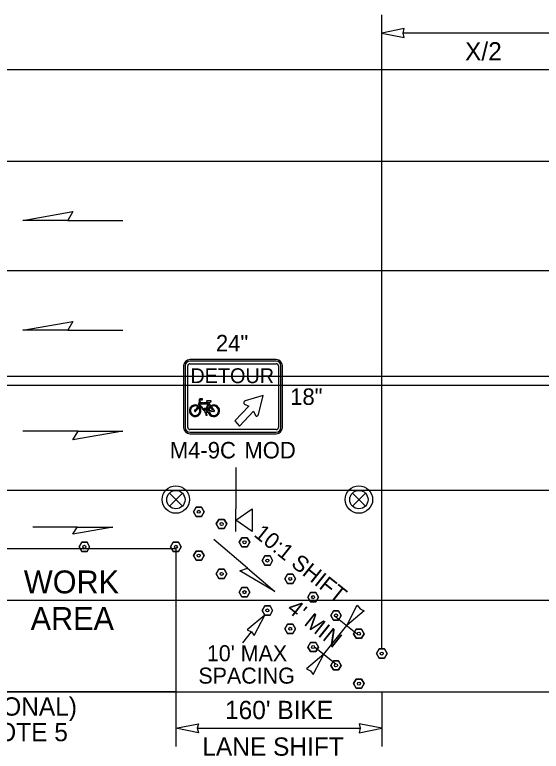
# Model space of a CAD drawing. Extents: x 99958 to 100176, y 99935 to 100011.
# Drawn here: x 100031.459 to 100033.761, y 99944.475 to 99947.696 of the extents above; entities that cross this region are included whole.
import ezdxf

# ---------------------------------------------------------------- set-up
doc = ezdxf.new("R2010")
doc.units = 0
for name, color, linetype in [('RD_ED_ShoulderPavedEdge', 7, 'Continuous'), ('RD_MK_LineDblYellowCenter', 7, 'Continuous'), ('RD_MK_LineEdgeWhite', 7, 'Continuous'), ('RD_MK_LineLane', 7, 'Continuous'), ('TR_SN_ConstructionSigns', 7, 'Continuous'), ('TR_WZ_PortableSignMountBlk-Org', 7, 'Continuous'), ('TR_WZ_TrafficSafetyDrum', 7, 'Continuous'), ('TR_WZ_TubularMarker', 7, 'Continuous'), ('TR_WZ_WorkAreaLabel', 7, 'Continuous'), ('TR_WZ_WorkZoneDetails', 7, 'Continuous'), ('TR_WZ_WorkZoneTextCurrent', 7, 'Continuous')]:
    doc.layers.add(name, color=color, linetype=linetype)

msp = doc.modelspace()

# ---------------------------------------------------------------- linework, layer by layer
at = {"layer": 'RD_ED_ShoulderPavedEdge'}
for p, q in [((100021.7266, 99947.4557), (100034.8933, 99947.4557)), ((100021.7266, 99944.7357), (100034.8933, 99944.7357))]:
    msp.add_line(p, q, dxfattribs=at)
at = {"layer": 'RD_MK_LineDblYellowCenter'}
for p, q in [((100021.7473, 99946.1157), (100034.914, 99946.1157)), ((100021.706, 99946.0757), (100034.8726, 99946.0757))]:
    msp.add_line(p, q, dxfattribs=at)
at = {"layer": 'RD_MK_LineEdgeWhite'}
for p, q in [((100021.7266, 99947.0557), (100034.8933, 99947.0557)), ((100021.7266, 99945.1357), (100034.8933, 99945.1357))]:
    msp.add_line(p, q, dxfattribs=at)
at = {"layer": 'RD_MK_LineLane'}
for points in [[(100034.8933, 99946.5757), (100021.7266, 99946.5757)], [(100034.8933, 99945.6157), (100021.7266, 99945.6157)]]:
    msp.add_lwpolyline(points, dxfattribs=at)
at = {"layer": 'TR_SN_ConstructionSigns'}
for p, q in [((100032.6025, 99946.1877), (100032.2245, 99946.1877)), ((100032.1975, 99946.1607), (100032.1975, 99945.8907)), ((100032.2042, 99946.1607), (100032.2042, 99945.8907)), ((100032.2155, 99945.8907), (100032.2155, 99946.1607)), ((100032.6025, 99946.181), (100032.2245, 99946.181)), ((100032.2245, 99946.1697), (100032.6025, 99946.1697)), ((100032.6115, 99946.1607), (100032.6115, 99945.8907)), ((100032.6227, 99945.8907), (100032.6227, 99946.1607)), ((100032.6295, 99945.8907), (100032.6295, 99946.1607)), ((100032.2675, 99946.0076), (100032.2604, 99945.9864)), ((100032.269, 99946.0156), (100032.2643, 99946.0108)), ((100032.2643, 99946.0108), (100032.2675, 99946.0076)), ((100032.2666, 99945.992), (100032.2675, 99945.9946)), ((100032.2675, 99945.9946), (100032.3033, 99945.9946)), ((100032.2802, 99946.0156), (100032.269, 99946.0156)), ((100032.269, 99945.9991), (100032.2718, 99946.0076)), ((100032.3048, 99945.9991), (100032.269, 99945.9991)), ((100032.2691, 99946.0103), (100032.2706, 99946.0118)), ((100032.2718, 99946.0076), (100032.2691, 99946.0103)), ((100032.2706, 99946.0118), (100032.2802, 99946.0118)), ((100032.2802, 99946.0118), (100032.2802, 99946.0156)), ((100032.3033, 99945.9946), (100032.2935, 99945.9651)), ((100032.2978, 99946.0041), (100032.298, 99946.0039)), ((100032.3156, 99946.0079), (100032.2987, 99946.0068)), ((100032.3056, 99946.0014), (100032.3048, 99945.9991)), ((100032.309, 99945.9975), (100032.3072, 99945.9922)), ((100032.3166, 99945.9863), (100032.309, 99945.9975)), ((100032.3168, 99946.0036), (100032.317, 99946.0038)), ((100032.247, 99945.9675), (100032.247, 99945.9676)), ((100032.2512, 99945.9651), (100032.2511, 99945.9651)), ((100032.2589, 99945.9821), (100032.2589, 99945.9821)), ((100032.2639, 99945.984), (100032.2624, 99945.9794)), ((100032.265, 99945.9872), (100032.2666, 99945.992)), ((100032.2902, 99945.9664), (100032.2666, 99945.992)), ((100032.2938, 99945.9737), (100032.2879, 99945.9737)), ((100032.2893, 99945.9715), (100032.2902, 99945.9664)), ((100032.2935, 99945.9651), (100032.2923, 99945.9715)), ((100032.2923, 99945.9715), (100032.2938, 99945.9715)), ((100032.2938, 99945.9715), (100032.2938, 99945.9737)), ((100032.2972, 99945.962), (100032.3072, 99945.9922)), ((100032.304, 99945.963), (100032.2972, 99945.962)), ((100032.3072, 99945.9922), (100032.313, 99945.9837)), ((100032.3249, 99945.9662), (100032.3084, 99945.9637)), ((100032.309, 99945.9593), (100032.327, 99945.9619)), ((100032.313, 99945.9837), (100032.3155, 99945.98)), ((100032.3155, 99945.98), (100032.313, 99945.9837)), ((100032.3155, 99945.98), (100032.3249, 99945.9662)), ((100032.3293, 99945.9677), (100032.3192, 99945.9826)), ((100032.2929, 99945.9546), (100032.2953, 99945.9472)), ((100032.2953, 99945.9472), (100032.2941, 99945.9472)), ((100032.2941, 99945.9472), (100032.2941, 99945.945)), ((100032.2941, 99945.945), (100032.3001, 99945.945)), ((100032.2985, 99945.9472), (100032.2957, 99945.9555)), ((100032.2969, 99945.9575), (100032.3046, 99945.9586)), ((100032.3001, 99945.9472), (100032.2985, 99945.9472)), ((100032.3001, 99945.945), (100032.3001, 99945.9472)), ((100032.3046, 99945.9586), (100032.309, 99945.9593)), ((100032.309, 99945.9593), (100032.3046, 99945.9586)), ((100032.6025, 99945.8817), (100032.2245, 99945.8817)), ((100032.2245, 99945.8705), (100032.6025, 99945.8705)), ((100032.2245, 99945.8637), (100032.6025, 99945.8637))]:
    msp.add_line(p, q, dxfattribs=at)
for points in [[(100032.5454, 99946.0301), (100032.4664, 99946.0069), (100032.4653, 99946.0065), (100032.4635, 99946.0053), (100032.4623, 99946.0039), (100032.4613, 99946.0021), (100032.4606, 99945.9997), (100032.4608, 99945.9973), (100032.4613, 99945.9958), (100032.4625, 99945.9942), (100032.4641, 99945.9932), (100032.4819, 99945.9848), (100032.4209, 99945.9198), (100032.442, 99945.8973), (100032.5027, 99945.962), (100032.5115, 99945.9436), (100032.512, 99945.9429), (100032.5127, 99945.942), (100032.5134, 99945.9415), (100032.5142, 99945.941), (100032.5153, 99945.9407), (100032.5163, 99945.9406), (100032.5175, 99945.9407), (100032.5194, 99945.9413), (100032.5204, 99945.9418), (100032.5212, 99945.9424), (100032.5221, 99945.9433), (100032.5231, 99945.9446), (100032.5237, 99945.9458), (100032.5242, 99945.9473), (100032.5454, 99946.0301)], [(100032.2978, 99946.0041), (100032.2978, 99946.0041)], [(100032.298, 99946.0039), (100032.298, 99946.0039)], [(100032.3072, 99945.9922), (100032.309, 99945.9975), (100032.3104, 99946.0015)], [(100032.3168, 99946.0036), (100032.3168, 99946.0036)], [(100032.317, 99946.0038), (100032.317, 99946.0038)], [(100032.2624, 99945.9794), (100032.2639, 99945.984), (100032.265, 99945.9872)], [(100032.2666, 99945.992), (100032.265, 99945.9872), (100032.29, 99945.9601)], [(100032.2879, 99945.9737), (100032.2879, 99945.9715), (100032.2893, 99945.9715)]]:
    msp.add_lwpolyline(points, dxfattribs=at)
for centre, radius, start, end in [((100032.2245, 99946.1607), 0.027, 90, 180), ((100032.6025, 99946.1607), 0.027, 360, 90), ((100032.2245, 99946.1607), 0.0203, 90, 180), ((100032.2245, 99946.1607), 0.009, 90, 180), ((100032.6025, 99946.1607), 0.0203, 0, 90), ((100032.6025, 99946.1607), 0.009, 360, 90), ((100032.2987, 99946.0053), 0.00149, 89.3854, 233.368), ((100032.3159, 99946.0057), 0.00224, 301.1219, 96.4128), ((100032.2479, 99945.9643), 0.0254, 60.5529, 50.868), ((100032.2479, 99945.9643), 0.0209, 58.1532, 46.1649), ((100032.2479, 99945.9643), 0.00336, 105.257, 14.3233), ((100032.3293, 99945.9643), 0.0254, 130.0889, 182.8379), ((100032.3293, 99945.9643), 0.0254, 192.9622, 119.9648), ((100032.3293, 99945.9643), 0.0209, 131.3616, 181.6359), ((100032.3293, 99945.9643), 0.0209, 193.937, 119.0598), ((100032.3293, 99945.9643), 0.00336, 225.1095, 90.4672), ((100032.2932, 99945.9583), 0.00374, 151.1744, 264.8566), ((100032.2932, 99945.9583), 0.00374, 312.0053, 347.2932), ((100032.2245, 99945.8907), 0.027, 180, 270), ((100032.2245, 99945.8907), 0.0202, 180, 270), ((100032.2245, 99945.8907), 0.009, 180, 270), ((100032.6025, 99945.8907), 0.027, 270, 0), ((100032.6025, 99945.8907), 0.0203, 270, 0), ((100032.6025, 99945.8907), 0.009, 270, 0)]:
    msp.add_arc(centre, radius, start, end, dxfattribs=at)
for centre, major_axis, ratio, start_param, end_param in [((100032.3076, 99946.0088), (-0.0127, 0), 0.588235, 0.712928, 1.410588), ((100032.3076, 99946.0088), (-0.0127, 0), 0.588235, 1.786993, 2.376237), ((100032.2512, 99945.9784), (-0.0072, -0.0108), 0.413554, 0.494612, 2.170849), ((100032.2512, 99945.9784), (-0.0095, -0.0143), 0.55814, 0.868091, 1.989998)]:
    msp.add_ellipse(centre, major_axis=major_axis, ratio=ratio, start_param=start_param, end_param=end_param, dxfattribs=at)
at = {"layer": 'TR_WZ_PortableSignMountBlk-Org'}
msp.add_line((100032.4251, 99945.4357), (100032.4251, 99945.5357), dxfattribs=at)
msp.add_lwpolyline([(100032.4251, 99945.4856), (100032.4969, 99945.5357), (100032.4969, 99945.4357)], close=True, dxfattribs=at)
at = {"layer": 'TR_WZ_TrafficSafetyDrum'}
for p, q in [((100032.1353, 99945.604), (100032.1919, 99945.5474)), ((100032.1919, 99945.604), (100032.1353, 99945.5474)), ((100032.1353, 99945.604), (100032.1919, 99945.5474)), ((100032.1919, 99945.604), (100032.1353, 99945.5474)), ((100032.9353, 99945.604), (100032.9919, 99945.5474)), ((100032.9919, 99945.604), (100032.9353, 99945.5474)), ((100032.9353, 99945.604), (100032.9919, 99945.5474)), ((100032.9919, 99945.604), (100032.9353, 99945.5474))]:
    msp.add_line(p, q, dxfattribs=at)
for centre, radius in [((100032.1636, 99945.5757), 0.06), ((100032.1636, 99945.5757), 0.06), ((100032.1636, 99945.5757), 0.06), ((100032.1636, 99945.5757), 0.06), ((100032.1636, 99945.5757), 0.04), ((100032.1636, 99945.5757), 0.04), ((100032.9636, 99945.5757), 0.06), ((100032.9636, 99945.5757), 0.06), ((100032.9636, 99945.5757), 0.06), ((100032.9636, 99945.5757), 0.06), ((100032.9636, 99945.5757), 0.04), ((100032.9636, 99945.5757), 0.04)]:
    msp.add_circle(centre, radius, dxfattribs=at)
at = {"layer": 'TR_WZ_TubularMarker'}
for points in [[(100032.2867, 99945.5224), (100032.2751, 99945.5424), (100032.252, 99945.5424), (100032.2405, 99945.5224), (100032.252, 99945.5024), (100032.2751, 99945.5024)], [(100032.3866, 99945.469), (100032.3751, 99945.489), (100032.352, 99945.489), (100032.3404, 99945.469), (100032.352, 99945.449), (100032.3751, 99945.449)], [(100031.7405, 99945.3691), (100031.7521, 99945.3891), (100031.7752, 99945.3891), (100031.7867, 99945.3691), (100031.7752, 99945.3491), (100031.7521, 99945.3491)], [(100032.1405, 99945.3691), (100032.1521, 99945.3891), (100032.1752, 99945.3891), (100032.1867, 99945.3691), (100032.1752, 99945.3491), (100032.1521, 99945.3491)], [(100032.4866, 99945.389), (100032.4751, 99945.409), (100032.452, 99945.409), (100032.4404, 99945.389), (100032.452, 99945.369), (100032.4751, 99945.369)], [(100032.2866, 99945.3308), (100032.2751, 99945.3508), (100032.252, 99945.3508), (100032.2404, 99945.3308), (100032.252, 99945.3108), (100032.2751, 99945.3108)], [(100032.5866, 99945.309), (100032.5751, 99945.329), (100032.552, 99945.329), (100032.5404, 99945.309), (100032.552, 99945.289), (100032.5751, 99945.289)], [(100032.3866, 99945.2508), (100032.3751, 99945.2708), (100032.352, 99945.2708), (100032.3404, 99945.2508), (100032.352, 99945.2308), (100032.3751, 99945.2308)], [(100032.6866, 99945.229), (100032.6751, 99945.249), (100032.652, 99945.249), (100032.6404, 99945.229), (100032.652, 99945.209), (100032.6751, 99945.209)], [(100032.4866, 99945.1708), (100032.4751, 99945.1908), (100032.452, 99945.1908), (100032.4404, 99945.1708), (100032.452, 99945.1508), (100032.4751, 99945.1508)], [(100032.7866, 99945.149), (100032.7751, 99945.169), (100032.752, 99945.169), (100032.7404, 99945.149), (100032.752, 99945.129), (100032.7751, 99945.129)], [(100032.5866, 99945.0908), (100032.5751, 99945.1108), (100032.552, 99945.1108), (100032.5404, 99945.0908), (100032.552, 99945.0708), (100032.5751, 99945.0708)], [(100032.8866, 99945.0691), (100032.8751, 99945.0891), (100032.852, 99945.0891), (100032.8404, 99945.0691), (100032.852, 99945.0491), (100032.8751, 99945.0491)], [(100032.6866, 99945.0108), (100032.6751, 99945.0308), (100032.652, 99945.0308), (100032.6404, 99945.0108), (100032.652, 99944.9908), (100032.6751, 99944.9908)], [(100032.9866, 99944.9891), (100032.9751, 99945.0091), (100032.952, 99945.0091), (100032.9404, 99944.9891), (100032.952, 99944.9691), (100032.9751, 99944.9691)], [(100032.7866, 99944.9308), (100032.7751, 99944.9508), (100032.752, 99944.9508), (100032.7404, 99944.9308), (100032.752, 99944.9108), (100032.7751, 99944.9108)], [(100033.0866, 99944.9024), (100033.0751, 99944.9224), (100033.052, 99944.9224), (100033.0404, 99944.9024), (100033.052, 99944.8824), (100033.0751, 99944.8824)], [(100032.8866, 99944.8508), (100032.8751, 99944.8708), (100032.852, 99944.8708), (100032.8404, 99944.8508), (100032.852, 99944.8308), (100032.8751, 99944.8308)], [(100032.9866, 99944.7708), (100032.9751, 99944.7908), (100032.952, 99944.7908), (100032.9404, 99944.7708), (100032.952, 99944.7508), (100032.9751, 99944.7508)]]:
    msp.add_lwpolyline(points, close=True, dxfattribs=at)
for points in [[(100032.2751, 99945.5024), (100032.252, 99945.5024), (100032.2405, 99945.5224), (100032.252, 99945.5424), (100032.2751, 99945.5424), (100032.2867, 99945.5224), (100032.2751, 99945.5024)], [(100032.3751, 99945.449), (100032.352, 99945.449), (100032.3404, 99945.469), (100032.352, 99945.489), (100032.3751, 99945.489), (100032.3866, 99945.469), (100032.3751, 99945.449)], [(100031.7521, 99945.3491), (100031.7752, 99945.3491), (100031.7867, 99945.3691), (100031.7752, 99945.3891), (100031.7521, 99945.3891), (100031.7405, 99945.3691), (100031.7521, 99945.3491)], [(100032.1521, 99945.3491), (100032.1752, 99945.3491), (100032.1867, 99945.3691), (100032.1752, 99945.3891), (100032.1521, 99945.3891), (100032.1405, 99945.3691), (100032.1521, 99945.3491)], [(100032.4751, 99945.369), (100032.452, 99945.369), (100032.4404, 99945.389), (100032.452, 99945.409), (100032.4751, 99945.409), (100032.4866, 99945.389), (100032.4751, 99945.369)], [(100032.2751, 99945.3108), (100032.252, 99945.3108), (100032.2404, 99945.3308), (100032.252, 99945.3508), (100032.2751, 99945.3508), (100032.2866, 99945.3308), (100032.2751, 99945.3108)], [(100032.5751, 99945.289), (100032.552, 99945.289), (100032.5404, 99945.309), (100032.552, 99945.329), (100032.5751, 99945.329), (100032.5866, 99945.309), (100032.5751, 99945.289)], [(100032.3751, 99945.2308), (100032.352, 99945.2308), (100032.3404, 99945.2508), (100032.352, 99945.2708), (100032.3751, 99945.2708), (100032.3866, 99945.2508), (100032.3751, 99945.2308)], [(100032.6751, 99945.209), (100032.652, 99945.209), (100032.6404, 99945.229), (100032.652, 99945.249), (100032.6751, 99945.249), (100032.6866, 99945.229), (100032.6751, 99945.209)], [(100032.4751, 99945.1508), (100032.452, 99945.1508), (100032.4404, 99945.1708), (100032.452, 99945.1908), (100032.4751, 99945.1908), (100032.4866, 99945.1708), (100032.4751, 99945.1508)], [(100032.7751, 99945.129), (100032.752, 99945.129), (100032.7404, 99945.149), (100032.752, 99945.169), (100032.7751, 99945.169), (100032.7866, 99945.149), (100032.7751, 99945.129)], [(100032.5751, 99945.0708), (100032.552, 99945.0708), (100032.5404, 99945.0908), (100032.552, 99945.1108), (100032.5751, 99945.1108), (100032.5866, 99945.0908), (100032.5751, 99945.0708)], [(100032.8751, 99945.0491), (100032.852, 99945.0491), (100032.8404, 99945.0691), (100032.852, 99945.0891), (100032.8751, 99945.0891), (100032.8866, 99945.0691), (100032.8751, 99945.0491)], [(100032.6751, 99944.9908), (100032.652, 99944.9908), (100032.6404, 99945.0108), (100032.652, 99945.0308), (100032.6751, 99945.0308), (100032.6866, 99945.0108), (100032.6751, 99944.9908)], [(100032.9751, 99944.9691), (100032.952, 99944.9691), (100032.9404, 99944.9891), (100032.952, 99945.0091), (100032.9751, 99945.0091), (100032.9866, 99944.9891), (100032.9751, 99944.9691)], [(100032.7751, 99944.9108), (100032.752, 99944.9108), (100032.7404, 99944.9308), (100032.752, 99944.9508), (100032.7751, 99944.9508), (100032.7866, 99944.9308), (100032.7751, 99944.9108)], [(100033.0751, 99944.8824), (100033.052, 99944.8824), (100033.0404, 99944.9024), (100033.052, 99944.9224), (100033.0751, 99944.9224), (100033.0866, 99944.9024), (100033.0751, 99944.8824)], [(100032.8751, 99944.8308), (100032.852, 99944.8308), (100032.8404, 99944.8508), (100032.852, 99944.8708), (100032.8751, 99944.8708), (100032.8866, 99944.8508), (100032.8751, 99944.8308)], [(100032.9751, 99944.7508), (100032.952, 99944.7508), (100032.9404, 99944.7708), (100032.952, 99944.7908), (100032.9751, 99944.7908), (100032.9866, 99944.7708), (100032.9751, 99944.7508)]]:
    msp.add_lwpolyline(points, dxfattribs=at)
for centre in [(100032.2636, 99945.5224), (100032.3635, 99945.469), (100032.4635, 99945.389), (100031.7636, 99945.3691), (100032.1636, 99945.3691), (100032.2635, 99945.3308), (100032.5635, 99945.309), (100032.3635, 99945.2508), (100032.6635, 99945.229), (100032.4635, 99945.1708), (100032.7635, 99945.149), (100032.5635, 99945.0908), (100032.8635, 99945.0691), (100032.6635, 99945.0108), (100032.9635, 99944.9891), (100032.7635, 99944.9308), (100033.0635, 99944.9024), (100032.8635, 99944.8508), (100032.9635, 99944.7708)]:
    msp.add_circle(centre, 0.00667, dxfattribs=at)
at = {"layer": 'TR_WZ_WorkZoneDetails'}
for p, q in [((100033.0636, 99944.9224), (100033.0636, 99947.6957)), ((100033.8549, 99947.6157), (100033.1573, 99947.6157)), ((100031.6913, 99946.7964), (100031.9324, 99946.7964)), ((100031.6913, 99946.3164), (100031.9324, 99946.3164)), ((100031.7359, 99945.875), (100031.4948, 99945.875)), ((100032.4251, 99945.7157), (100032.4251, 99945.5357)), ((100031.7314, 99945.4557), (100031.5385, 99945.4557)), ((100032.4766, 99945.2761), (100032.3295, 99945.4008)), ((100032.8635, 99945.0624), (100032.957, 99944.9876)), ((100032.4934, 99944.9976), (100032.4545, 99944.9489)), ((100032.8103, 99944.9), (100032.9103, 99945.025)), ((100032.77, 99944.9323), (100032.8635, 99944.8575)), ((100032.1636, 99944.7357), (100032.1636, 99944.4957)), ((100033.0636, 99944.7357), (100033.0636, 99944.4957)), ((100032.2573, 99944.5757), (100032.9698, 99944.5757))]:
    msp.add_line(p, q, dxfattribs=at)
for points in [[(100033.0636, 99947.6157), (100033.1619, 99947.5965), (100033.1573, 99947.6157), (100033.1619, 99947.635)], [(100031.4948, 99946.7964), (100031.7136, 99946.835), (100031.6913, 99946.7964)], [(100031.4948, 99946.3164), (100031.7136, 99946.355), (100031.6913, 99946.3164)], [(100031.9324, 99945.875), (100031.7136, 99945.8364), (100031.7359, 99945.875)], [(100031.8886, 99945.4557), (100031.7136, 99945.4249), (100031.7314, 99945.4557)], [(100030.4636, 99944.7357), (100030.4636, 99945.3624), (100032.1636, 99945.3624), (100032.1636, 99944.7357)], [(100032.5965, 99945.1744), (100032.443, 99945.2641), (100032.4766, 99945.2761)], [(100032.9103, 99945.025), (100032.9566, 99945.1138), (100032.9688, 99945.0982), (100032.9867, 99945.0897)], [(100032.552, 99945.0708), (100032.4756, 99945.006), (100032.4935, 99944.9976), (100032.5057, 99944.982)], [(100032.8103, 99944.9), (100032.7339, 99944.8353), (100032.7518, 99944.8269), (100032.764, 99944.8113)], [(100032.1636, 99944.5757), (100032.2619, 99944.595), (100032.2573, 99944.5757), (100032.2619, 99944.5565)], [(100033.0636, 99944.5757), (100032.9653, 99944.595), (100032.9698, 99944.5757), (100032.9653, 99944.5565)]]:
    msp.add_lwpolyline(points, close=True, dxfattribs=at)

# ---------------------------------------------------------------- texts
at = {"layer": 'TR_SN_ConstructionSigns'}
for s, height, p in [('24"', 0.072, (100032.3387, 99946.2237)), ('DETOUR', 0.0648, (100032.2269, 99946.0849)), ('18"', 0.072, (100032.6633, 99945.9897)), ('M4-9C', 0.072, (100032.1371, 99945.7557)), ('MOD', 0.072, (100032.4631, 99945.7557))]:
    msp.add_text(s, height=height, rotation=360, dxfattribs=at).set_placement(p)
at = {"layer": 'TR_WZ_WorkAreaLabel'}
for s, p in [('WORK', (100031.499, 99945.1657)), ('AREA', (100031.5287, 99945.0057))]:
    msp.add_text(s, height=0.1, dxfattribs=at).set_placement(p)
at = {"layer": 'TR_WZ_WorkZoneTextCurrent'}
for s, height, p in [('X/2', 0.08, (100033.4276, 99947.4957)), ("10' MAX", 0.07, (100032.2991, 99944.8689)), ('SPACING', 0.07, (100032.262, 99944.7709)), ('(OPTIONAL)', 0.08, (100031.119, 99944.631)), ("160' BIKE", 0.08, (100032.3784, 99944.6157)), ('SEE NOTE 5', 0.08, (100031.0614, 99944.519)), ('LANE SHIFT', 0.08, (100032.2792, 99944.4557))]:
    msp.add_text(s, height=height, dxfattribs=at).set_placement(p)
for s, p in [('10:1 SHIFT', (100032.5004, 99945.418)), ("4' MIN", (100032.6446, 99945.0903))]:
    msp.add_text(s, height=0.07, rotation=321.3417, dxfattribs=at).set_placement(p)

doc.saveas('drawing.dxf')
